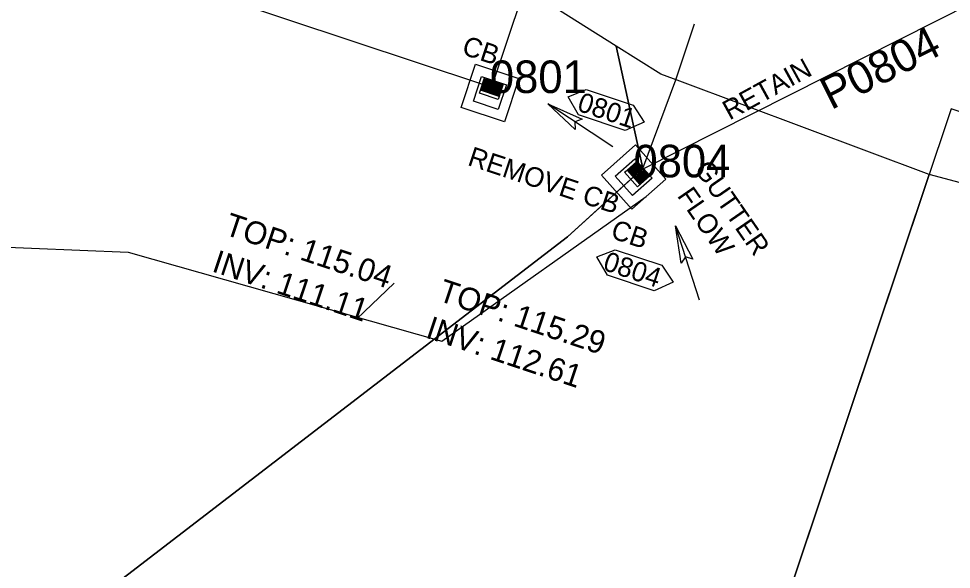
# Model space of a CAD drawing. Extents: x 2296558 to 2299313, y 599200 to 601383.
# Drawn here: x 2298959.5 to 2299102.6, y 599410.6 to 599495.2 of the extents above; entities that cross this region are included whole.
import ezdxf

# ---------------------------------------------------------------- set-up
doc = ezdxf.new("R2010")
doc.units = 0
for name, color, linetype in [('Prop Drainage Structure Box Number Symbol CELL', 7, 'Continuous'), ('Prop Drainage Structure Catch Basin Grate 840 03F CELL', 7, 'Continuous'), ('Prop Drainage Structure Catch Basin Grate 840 03F Label', 7, 'Continuous'), ('Prop Drainage Structure Catch Basin Grate 840 03G CELL', 7, 'Continuous'), ('Prop Drainage Structure Pipe RCP 15in Class IV', 7, 'Continuous'), ('Prop Drainage Structure Pipe RCP 18in Class IV', 7, 'Continuous'), ('Prop Drainage Structure Plot Symbol 20 Scale', 7, 'Continuous'), ('Prop Drainage Structure Plot Symbol 50 Scale', 7, 'Continuous'), ('Prop Drainage Structure Removal Label', 7, 'Continuous'), ('Prop Drainage Structure Retain Label', 7, 'Continuous'), ('Prop Drainage Structure Tops and Inverts LABEL', 7, 'Continuous'), ('Prop Plan Preparation Grade to Drain Arrows CELL', 7, 'Continuous'), ('Prop Plan Preparation Grade to Drain Arrows Label', 7, 'Continuous'), ('Prop Plan Preparation Watershed Post Construction', 7, 'Continuous'), ('Scratch_Level_1', 7, 'Continuous'), ('Scratch_Level_3', 7, 'Continuous'), ('Scratch_Level_5', 7, 'Continuous'), ('Scratch_Level_9', 7, 'Continuous')]:
    doc.layers.add(name, color=color, linetype=linetype)

msp = doc.modelspace()

# ---------------------------------------------------------------- linework, layer by layer
at = {"layer": 'Prop Drainage Structure Box Number Symbol CELL'}
for points in [[(2299046.59, 599484.3), (2299053.76, 599481.91), (2299055.49, 599479.3), (2299052.57, 599478), (2299045.39, 599480.39), (2299043.79, 599483.18), (2299046.59, 599484.3)], [(2299051.02, 599459.68), (2299058.19, 599457.3), (2299059.92, 599454.69), (2299057, 599453.39), (2299049.82, 599455.78), (2299048.22, 599458.57), (2299051.02, 599459.68)]]:
    msp.add_lwpolyline(points, dxfattribs=at)
at = {"layer": 'Prop Drainage Structure Catch Basin Grate 840 03F CELL'}
for p, q in [((2299031.02, 599485.44), (2299031.79, 599483.97)), ((2299031.11, 599485.7), (2299031.88, 599484.22)), ((2299031.27, 599485.83), (2299031.97, 599484.48)), ((2299032, 599484.57), (2299031.43, 599485.68)), ((2299032.17, 599485.1), (2299031.96, 599485.5)), ((2299032.41, 599485.61), (2299032.41, 599485.61)), ((2299030.6, 599484.27), (2299030.57, 599484.33)), ((2299030.87, 599484.18), (2299030.65, 599484.59)), ((2299030.68, 599485.13), (2299030.68, 599485.13)), ((2299030.68, 599484.39), (2299030.71, 599484.32)), ((2299031.14, 599484.09), (2299030.74, 599484.85)), ((2299030.76, 599484.65), (2299030.98, 599484.24)), ((2299031.41, 599484), (2299030.83, 599485.12)), ((2299030.85, 599484.91), (2299031.25, 599484.15)), ((2299031.67, 599483.91), (2299030.91, 599485.38)), ((2299030.94, 599485.17), (2299031.52, 599484.06)), ((2299031.96, 599484.06), (2299032.05, 599483.88)), ((2299032.05, 599484.32), (2299032.32, 599483.79)), ((2299032.11, 599484.7), (2299032.11, 599484.7)), ((2299032.13, 599484.59), (2299032.59, 599483.7)), ((2299032.22, 599484.85), (2299032.86, 599483.61)), ((2299032.31, 599485.11), (2299033.13, 599483.52)), ((2299033.11, 599483.72), (2299032.34, 599485.21)), ((2299033.19, 599483.99), (2299032.5, 599485.32)), ((2299032.61, 599485.38), (2299033.31, 599484.04)), ((2299033.28, 599484.25), (2299032.77, 599485.24)), ((2299032.88, 599485.29), (2299033.39, 599484.31)), ((2299033.37, 599484.51), (2299033.04, 599485.15)), ((2299033.15, 599485.2), (2299033.48, 599484.57)), ((2299033.46, 599484.77), (2299033.31, 599485.06)), ((2299033.42, 599485.11), (2299033.57, 599484.83)), ((2299033.52, 599484.2), (2299033.52, 599484.2)), ((2299031.62, 599483.24), (2299031.62, 599483.24))]:
    msp.add_line(p, q, dxfattribs=at)
for points in [[(2299033.2, 599483.24), (2299030.35, 599484.19), (2299030.98, 599486.08), (2299033.83, 599485.14), (2299033.04, 599482.77), (2299030.2, 599483.71), (2299030.35, 599484.19)], [(2299030.37, 599484.19), (2299030.99, 599486.07), (2299033.82, 599485.13), (2299033.2, 599483.25), (2299030.37, 599484.19)], [(2299033.04, 599483.44), (2299030.53, 599484.27), (2299031.07, 599485.91), (2299033.66, 599485.05), (2299033.14, 599483.47)], [(2299031.88, 599484.22), (2299031.82, 599484.05), (2299031, 599485.64)], [(2299031.97, 599484.48), (2299031.91, 599484.31), (2299031.16, 599485.77)], [(2299031.54, 599485.74), (2299032.05, 599484.74), (2299032, 599484.57)], [(2299031.81, 599485.65), (2299032.14, 599485), (2299032.09, 599484.84), (2299031.69, 599485.59)], [(2299032.23, 599485.26), (2299032.17, 599485.1), (2299031.96, 599485.5)], [(2299032.07, 599485.56), (2299032.23, 599485.26), (2299032.17, 599485.1)], [(2299031.94, 599483.82), (2299031.9, 599483.89), (2299031.96, 599484.06)], [(2299032.21, 599483.73), (2299031.99, 599484.16), (2299032.05, 599484.32)], [(2299032.48, 599483.64), (2299032.08, 599484.42), (2299032.13, 599484.59)], [(2299032.75, 599483.55), (2299032.17, 599484.68), (2299032.22, 599484.85)], [(2299033.02, 599483.46), (2299032.25, 599484.94), (2299032.31, 599485.11)], [(2299032.34, 599485.21), (2299032.4, 599485.37), (2299033.22, 599483.78)]]:
    msp.add_lwpolyline(points, dxfattribs=at)
for centre, start, end in [((2299030.97, 599485.41), 27.3644, 207.3644), ((2299031.06, 599485.67), 27.3644, 207.3644), ((2299031.21, 599485.8), 27.3644, 207.3644), ((2299031.48, 599485.71), 27.3644, 207.3644), ((2299031.75, 599485.62), 27.3644, 207.3644), ((2299032.02, 599485.53), 27.3644, 207.3644), ((2299032.56, 599485.35), 27.3644, 207.3644), ((2299030.62, 599484.36), 27.3644, 207.3644), ((2299030.65, 599484.3), 207.3644, 27.3644), ((2299030.71, 599484.62), 27.3644, 207.3644), ((2299030.8, 599484.88), 27.3644, 207.3644), ((2299030.88, 599485.15), 27.3644, 207.3644), ((2299030.92, 599484.21), 207.3644, 27.3644), ((2299031.19, 599484.12), 207.3644, 27.3644), ((2299031.46, 599484.03), 207.3644, 27.3644), ((2299031.73, 599483.94), 207.3644, 27.3644), ((2299032.83, 599485.26), 27.3644, 207.3644), ((2299033.1, 599485.17), 27.3644, 207.3644), ((2299033.25, 599484.01), 207.3644, 27.3644), ((2299033.34, 599484.28), 207.3636, 27.3636), ((2299033.36, 599485.09), 27.3644, 207.3644), ((2299033.42, 599484.54), 207.3636, 27.3636), ((2299033.51, 599484.8), 207.3644, 27.3644), ((2299032, 599483.85), 207.3644, 27.3644), ((2299032.27, 599483.76), 207.3644, 27.3644), ((2299032.54, 599483.67), 207.3644, 27.3644), ((2299032.81, 599483.58), 207.3644, 27.3644), ((2299033.08, 599483.49), 207.3644, 27.3644), ((2299033.16, 599483.75), 207.3644, 27.3644)]:
    msp.add_arc(centre, 0.0625, start, end, dxfattribs=at)
at = {"layer": 'Prop Drainage Structure Catch Basin Grate 840 03G CELL'}
for p, q in [((2299053.6, 599472.58), (2299053.6, 599472.58)), ((2299053.74, 599472.52), (2299054.85, 599472.44)), ((2299054.65, 599472.52), (2299053.94, 599472.58)), ((2299053.95, 599472.7), (2299054.66, 599472.65)), ((2299054.46, 599472.74), (2299054.14, 599472.76)), ((2299054.15, 599472.88), (2299054.47, 599472.86)), ((2299055.03, 599472.1), (2299053.52, 599472.21)), ((2299053.53, 599472.33), (2299055.04, 599472.23)), ((2299054.84, 599472.31), (2299053.73, 599472.39)), ((2299054.25, 599471.09), (2299055.92, 599470.97)), ((2299054.46, 599471.27), (2299055.98, 599471.17)), ((2299054.61, 599471.49), (2299054.61, 599471.49)), ((2299054.67, 599471.46), (2299055.79, 599471.38)), ((2299054.87, 599471.64), (2299055.6, 599471.59)), ((2299055.08, 599471.83), (2299055.41, 599471.8)), ((2299055.32, 599472.12), (2299055.32, 599472.12)), ((2299053.46, 599470.47), (2299053.46, 599470.47)), ((2299054.06, 599470.91), (2299055.71, 599470.79)), ((2299054.25, 599470.69), (2299055.51, 599470.6)), ((2299054.44, 599470.48), (2299055.3, 599470.42)), ((2299054.63, 599470.27), (2299055.09, 599470.24)), ((2299054.88, 599469.93), (2299054.81, 599469.93)), ((2299054.82, 599470.06), (2299054.89, 599470.05)), ((2299055.61, 599470.37), (2299055.61, 599470.37))]:
    msp.add_line(p, q, dxfattribs=at)
for points in [[(2299054.83, 599469.68), (2299052.84, 599471.92), (2299054.33, 599473.25), (2299056.32, 599471.01), (2299054.46, 599469.35), (2299052.46, 599471.59), (2299052.84, 599471.92)], [(2299054.83, 599469.69), (2299052.85, 599471.92), (2299054.33, 599473.23), (2299056.31, 599471.01), (2299054.83, 599469.69)], [(2299054.32, 599473.06), (2299056.13, 599471.02), (2299054.84, 599469.87), (2299053.03, 599471.91), (2299054.32, 599473.06)], [(2299053.12, 599471.97), (2299054.91, 599471.84), (2299054.78, 599471.72), (2299053.11, 599471.84)], [(2299053.31, 599471.75), (2299054.7, 599471.65), (2299054.57, 599471.54), (2299053.3, 599471.63)], [(2299053.33, 599472.15), (2299055.11, 599472.02), (2299054.98, 599471.91), (2299053.32, 599472.02)], [(2299053.5, 599471.54), (2299054.49, 599471.47), (2299054.36, 599471.35), (2299053.49, 599471.42)], [(2299053.69, 599471.33), (2299054.29, 599471.29), (2299054.16, 599471.17), (2299053.68, 599471.2)], [(2299053.88, 599471.12), (2299054.08, 599471.1), (2299053.95, 599470.99), (2299053.87, 599470.99)], [(2299055.91, 599470.85), (2299054.12, 599470.97), (2299054.25, 599471.09)], [(2299055.97, 599471.04), (2299054.33, 599471.16), (2299054.46, 599471.27)], [(2299055.78, 599471.25), (2299054.54, 599471.34), (2299054.67, 599471.46)], [(2299055.59, 599471.46), (2299054.74, 599471.53), (2299054.87, 599471.64)], [(2299055.4, 599471.68), (2299054.95, 599471.71), (2299055.08, 599471.83)], [(2299055.7, 599470.66), (2299054.05, 599470.78), (2299054.06, 599470.91)], [(2299055.5, 599470.48), (2299054.24, 599470.57), (2299054.25, 599470.69)], [(2299055.29, 599470.3), (2299054.43, 599470.36), (2299054.44, 599470.48)], [(2299055.09, 599470.11), (2299054.62, 599470.15), (2299054.63, 599470.27)]]:
    msp.add_lwpolyline(points, dxfattribs=at)
for centre, start, end in [((2299053.73, 599472.45), 85.9098, 265.9098), ((2299053.94, 599472.64), 85.9098, 265.9098), ((2299054.15, 599472.82), 85.9098, 265.9098), ((2299054.47, 599472.8), 265.9098, 85.9098), ((2299054.66, 599472.59), 265.9098, 85.9098), ((2299053.11, 599471.9), 85.9098, 265.9098), ((2299053.31, 599471.69), 85.9098, 265.9098), ((2299053.32, 599472.09), 85.9098, 265.9098), ((2299053.49, 599471.48), 85.9098, 265.9098), ((2299053.53, 599472.27), 85.9098, 265.9098), ((2299053.68, 599471.27), 85.9098, 265.9098), ((2299053.87, 599471.06), 85.9098, 265.9098), ((2299054.84, 599472.37), 265.9098, 85.9098), ((2299055.03, 599472.16), 265.9098, 85.9098), ((2299055.41, 599471.74), 265.9098, 85.9098), ((2299055.6, 599471.53), 265.9098, 85.9098), ((2299055.79, 599471.32), 265.9098, 85.9098), ((2299055.97, 599471.1), 265.9098, 85.9098), ((2299054.81, 599470), 85.9098, 265.9098), ((2299054.88, 599469.99), 265.9098, 85.9098), ((2299055.09, 599470.17), 265.9098, 85.9098), ((2299055.3, 599470.36), 265.9098, 85.9098), ((2299055.5, 599470.54), 265.9098, 85.9098), ((2299055.71, 599470.73), 265.9098, 85.9098), ((2299055.92, 599470.91), 265.9098, 85.9098)]:
    msp.add_arc(centre, 0.0625, start, end, dxfattribs=at)
at = {"layer": 'Prop Drainage Structure Pipe RCP 15in Class IV'}
msp.add_line((2298838.96, 599548.78), (2299030.68, 599485.13), dxfattribs=at)
at = {"layer": 'Prop Drainage Structure Pipe RCP 18in Class IV'}
msp.add_line((2299032.41, 599485.61), (2299043.77, 599519.83), dxfattribs=at)
at = {"layer": 'Prop Drainage Structure Plot Symbol 20 Scale'}
for points in [[(2299030.52, 599486.28), (2299034.32, 599485.02), (2299033.06, 599481.22), (2299029.26, 599482.48)], [(2299054.03, 599473.65), (2299056.69, 599470.66), (2299053.7, 599468), (2299051.04, 599470.99)]]:
    msp.add_lwpolyline(points, close=True, dxfattribs=at)
at = {"layer": 'Prop Drainage Structure Plot Symbol 50 Scale'}
for points in [[(2299029.57, 599488.18), (2299036.22, 599485.97), (2299034.01, 599479.33), (2299027.37, 599481.53)], [(2299054.15, 599475.77), (2299058.81, 599470.54), (2299053.57, 599465.89), (2299048.92, 599471.12)]]:
    msp.add_lwpolyline(points, close=True, dxfattribs=at)
at = {"layer": 'Prop Plan Preparation Grade to Drain Arrows CELL'}
for p, q in [((2299050.66, 599475.47), (2299040.67, 599482.11)), ((2299063.97, 599451.93), (2299060.28, 599463.35))]:
    msp.add_line(p, q, dxfattribs=at)
for points in [[(2299044.9, 599478.16), (2299040.67, 599482.11), (2299045.95, 599479.74), (2299044.83, 599479.34)], [(2299061.13, 599457.63), (2299060.28, 599463.35), (2299062.94, 599458.21), (2299061.82, 599458.59)]]:
    msp.add_lwpolyline(points, close=True, dxfattribs=at)
at = {"layer": 'Prop Plan Preparation Watershed Post Construction'}
for q in [(2299026.24, 599506.67), (2299051.16, 599490.96)]:
    msp.add_line((2299051.16, 599490.96), q, dxfattribs=at)
msp.add_lwpolyline([(2298834.87, 599541.22), (2298823.02, 599517.66), (2298813.49, 599507.05), (2298804.4, 599498.43), (2298791.26, 599476.48), (2298780.72, 599471.9), (2298840.07, 599450.26), (2298884.99, 599370.73), (2298946.55, 599387.03), (2299043.68, 599461.69), (2299055.28, 599472.17), (2299051.16, 599490.96)], dxfattribs=at)
for points in [[(2299043.68, 599461.69), (2298946.55, 599387.03), (2298884.99, 599370.73), (2298917.76, 599329.45), (2298985.68, 599301.81), (2299034.3, 599277.17), (2299099.24, 599471.26), (2299060.92, 599485.56), (2299058.03, 599486.63), (2299051.16, 599490.96), (2299055.28, 599472.17), (2299053.44, 599470.51)], [(2299034.3, 599277.17), (2299068.89, 599265.54), (2299164.35, 599258.21), (2299187.08, 599250.1), (2299278.03, 599200.45), (2299283.1, 599276.07), (2299285.25, 599366.73), (2299299.35, 599416.01), (2299147.02, 599458.5), (2299099.24, 599471.26)]]:
    msp.add_lwpolyline(points, close=True, dxfattribs=at)
at = {"layer": 'Scratch_Level_1'}
for p, q in [((2299060.35, 599485.77), (2299063.22, 599494.4)), ((2299055.28, 599472.17), (2299060.35, 599485.77)), ((2299024.41, 599445.64), (2299055.77, 599467.87)), ((2299017.11, 599454.56), (2299011.37, 599449.06))]:
    msp.add_line(p, q, dxfattribs=at)
for points in [[(2298653.47, 599601.76), (2298694.59, 599563.02), (2298748.03, 599565.3), (2298785.72, 599520.13), (2298837.27, 599516.71), (2298890.08, 599517.09), (2298924.3, 599461.48), (2298976.27, 599459.32), (2299024.41, 599445.64)], [(2299299.35, 599416.01), (2299118.35, 599476.09), (2299109.81, 599478.93), (2299102.61, 599481.32), (2299034.3, 599277.17)]]:
    msp.add_lwpolyline(points, dxfattribs=at)
at = {"layer": 'Scratch_Level_9'}
msp.add_line((2299055.32, 599472.12), (2299108.49, 599498.98), dxfattribs=at)

# ---------------------------------------------------------------- texts
at = {"layer": 'Prop Drainage Structure Box Number Symbol CELL'}
for s, p in [('0801', (2299045.03, 599481.09)), ('0804', (2299048.98, 599456.64))]:
    msp.add_text(s, height=3, rotation=341.6372, dxfattribs=at).set_placement(p)
at = {"layer": 'Prop Drainage Structure Catch Basin Grate 840 03F Label'}
for p in [(2299027.32, 599489.76), (2299050.17, 599461.53)]:
    msp.add_text('CB', height=3, rotation=341.6372, dxfattribs=at).set_placement(p)
at = {"layer": 'Prop Drainage Structure Removal Label'}
msp.add_text('REMOVE CB', height=3, rotation=341.6372, dxfattribs=at).set_placement((2299028.22, 599472.73))
at = {"layer": 'Prop Drainage Structure Retain Label'}
msp.add_text('RETAIN', height=3, rotation=28.7547, dxfattribs=at).set_placement((2299068.58, 599479.52))
at = {"layer": 'Prop Drainage Structure Tops and Inverts LABEL'}
for s, p in [('TOP: 115.04', (2298990.85, 599462.09)), ('INV: 111.11', (2298988.95, 599456.4)), ('TOP: 115.29', (2299023.65, 599451.92)), ('INV: 112.61', (2299021.75, 599446.23))]:
    msp.add_text(s, height=3.5, rotation=341.5664, dxfattribs=at).set_placement(p)
at = {"layer": 'Prop Plan Preparation Grade to Drain Arrows Label'}
for s, p in [('GUTTER', (2299063.08, 599472.07)), ('FLOW', (2299060.44, 599467.97))]:
    msp.add_text(s, height=3, rotation=304.6459, dxfattribs=at).set_placement(p)
at = {"layer": 'Scratch_Level_3'}
msp.add_text('P0804', height=5, rotation=26.7977, dxfattribs=at).set_placement((2299084.16, 599481.09))
at = {"layer": 'Scratch_Level_5'}
for s, p in [('0801', (2299031.79, 599483.75)), ('0804', (2299053.83, 599470.8))]:
    msp.add_text(s, height=5, dxfattribs=at).set_placement(p)

doc.saveas('drawing.dxf')
